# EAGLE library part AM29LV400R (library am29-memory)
4-Megabit FLASH MEMORY (512 K x 8 bit/256 K x 16 bit) CMOS 3 V-only boot sector flash memory
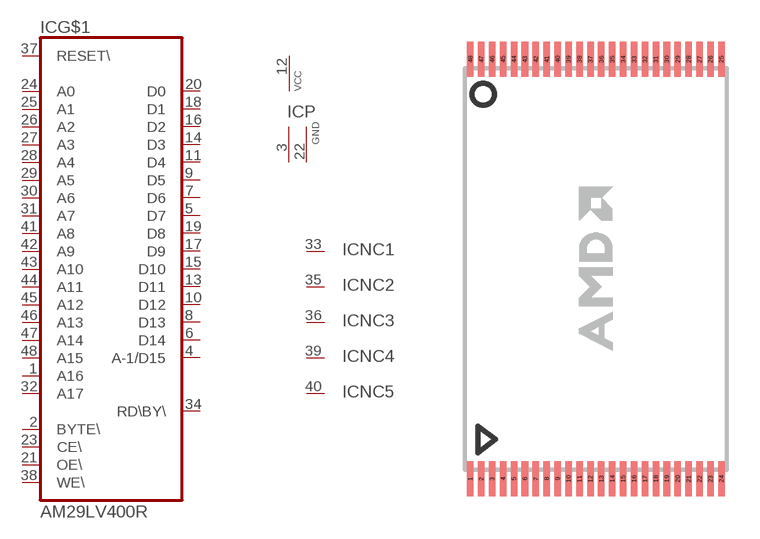
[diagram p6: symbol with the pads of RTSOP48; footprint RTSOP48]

Designator prefix IC; gates G$1=29LV400 P=VCC2GND NC1=NC NC2=NC NC3=NC NC4=NC NC5=NC

## AM29LV400R  [RTSOP48]
1  G$1:A16  in
2  G$1:BYTE\  in
3  P:GND  pwr
4  G$1:A-1/D15  hiz
5  G$1:D7  hiz
6  G$1:D14  hiz
7  G$1:D6  hiz
8  G$1:D13  hiz
9  G$1:D5  hiz
10  G$1:D12  hiz
11  G$1:D4  hiz
12  P:VCC  pwr
13  G$1:D11  hiz
14  G$1:D3  hiz
15  G$1:D10  hiz
16  G$1:D2  hiz
17  G$1:D9  hiz
18  G$1:D1  hiz
19  G$1:D8  hiz
20  G$1:D0  hiz
21  G$1:OE\  in
22  P:GND  pwr
23  G$1:CE\  in
24  G$1:A0  in
25  G$1:A1  in
26  G$1:A2  in
27  G$1:A3  in
28  G$1:A4  in
29  G$1:A5  in
30  G$1:A6  in
31  G$1:A7  in
32  G$1:A17  in
33  NC1:NC  nc
34  G$1:RD\BY\  out
35  NC2:NC  nc
36  NC3:NC  nc
37  G$1:RESET\  in
38  G$1:WE\  in
39  NC4:NC  nc
40  NC5:NC  nc
41  G$1:A8  in
42  G$1:A9  in
43  G$1:A10  in
44  G$1:A11  in
45  G$1:A12  in
46  G$1:A13  in
47  G$1:A14  in
48  G$1:A15  in

## Footprint RTSOP48 (pad centres in mm)
Reverse TSOP48
smd 0.3 x 1.6: 1 -5.75,-9.6; 2 -5.25,-9.6; 3 -4.75,-9.6; 4 -4.25,-9.6; 5 -3.75,-9.6; 6 -3.25,-9.6; 7 -2.75,-9.6; 8 -2.25,-9.6; 9 -1.75,-9.6; 10 -1.25,-9.6; 11 -0.75,-9.6; 12 -0.25,-9.6; 13 0.25,-9.6; 14 0.75,-9.6; 15 1.25,-9.6; 16 1.75,-9.6; 17 2.25,-9.6; 18 2.75,-9.6; 19 3.25,-9.6; 20 3.75,-9.6; 21 4.25,-9.6; 22 4.75,-9.6; 23 5.25,-9.6; 24 5.75,-9.6; 25 5.75,9.6; 26 5.25,9.6; 27 4.75,9.6; 28 4.25,9.6; 29 3.75,9.6; 30 3.25,9.6; 31 2.75,9.6; 32 2.25,9.6; 33 1.75,9.6; 34 1.25,9.6; 35 0.75,9.6; 36 0.25,9.6; 37 -0.25,9.6; 38 -0.75,9.6; 39 -1.25,9.6; 40 -1.75,9.6; 41 -2.25,9.6; 42 -2.75,9.6; 43 -3.25,9.6; 44 -3.75,9.6; 45 -4.25,9.6; 46 -4.75,9.6; 47 -5.25,9.6; 48 -5.75,9.6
